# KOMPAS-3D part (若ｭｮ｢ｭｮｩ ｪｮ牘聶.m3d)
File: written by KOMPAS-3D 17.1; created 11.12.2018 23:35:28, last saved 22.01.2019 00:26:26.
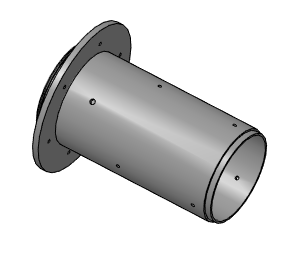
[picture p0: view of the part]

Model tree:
1. Эскиз:1
2. Операция вращения:1
     Угол 1 = 360
3. Плоскость отверстий у фланца
     Расстояние = 71.01
4. Крепежное отверстие 1
5. Крепежное отверстие 2
6. Крепежное отверстие 3
7. Вырезать элемент вращения:1
     Угол 1 = 360
8. Вырезать элемент вращения:2
     Угол 1 = 360
9. Вырезать элемент вращения:3
     Угол 1 = 360
10. Плоскость дальних у выходного отверстия
     Расстояние = 67.13
11. Крепежное отверстие 4
12. Вырезать элемент вращения:4
     Угол 1 = 360
13. Крепежное отверстие 5
14. Вырезать элемент вращения:5
     Угол 1 = 360
15. Крепежное отверстие 6
16. Вырезать элемент вращения:6
     Угол 1 = 360
17. Замок
18. Операция выдавливания:1
     Расстояние 1 = 3
19. Плоскость ограничителя фильтра
     Расстояние = 5
20. Буртик ограничителя фильтра
21. Операция выдавливания:2
     Расстояние 2 = 2
22. Паз ограничителя фильтра
23. Вырезать элемент выдавливания:1
     Расстояние 1 = 3
24. Массив по концентрической сетке:1  (with: Вырезать элемент выдавливания:1)  (4 pattern instances)
     Шаг 2 = 360
25. Плоскость фланца
     Расстояние = 13
26. Крепежный фланец
27. Операция выдавливания:5
     Расстояние 2 = 5
28. Плоскость крепежных отверстий
     Расстояние = 18
29. Отверстие под дюбель
30. Вырезать элемент выдавливания:2
     Расстояние 2 = 5
31. Массив по концентрической сетке:2  (with: Вырезать элемент выдавливания:2, Смещенная плоскость:7)  (6 pattern instances)
     Шаг 2 = 360
32. Эскиз:4
33. Операция вращения:2
     Угол 1 = 360
34. Соединительный вырез
35. Вырезать элемент выдавливания:3
     Расстояние 1 = 5
36. Эскиз:6
37. Смещенная плоскость:8
38. Отверстие под провод
39. Элемент вращения:1
     Угол 1 = 360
